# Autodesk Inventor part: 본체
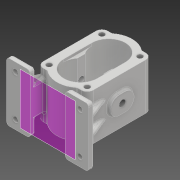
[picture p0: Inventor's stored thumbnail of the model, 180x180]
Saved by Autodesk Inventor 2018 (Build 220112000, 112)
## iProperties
Created: 2023-06
Part Number: 본체
Material: 일반
Document SubType Name: Modeling
Designer: 강의실01
Density: 1 g/cm^3
Appearance: 기본값
Mass: 469.209 g
Surface Area: 986.48 cm^2
Volume: 469.209 cm^3
Author: 강의실01
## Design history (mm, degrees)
sketch "스케치1"
  geometry: L1 (-42.5, -45)-(-42.5, 45); L2 (42.5, 45)-(42.5, -45); L3 (42.5, -55)-(-42.5, 55); L4 (-42.5, -55)-(42.5, 55); L5 (-24, -24)-(24, 24); L6 (24, -24)-(-24, 24); L7 (-32.5, 55)-(-25.278, 55); L8 (25.278, 55)-(32.5, 55); L9 (32.5, -55)-(25.278, -55); L10 (-25.278, -55)-(-32.5, -55); L11 (22.5, 6.507)-(22.5, -6.507); L12 (-22.5, -6.507)-(-22.5, 6.507); L13 (-22.5, 22.5)-(22.5, -22.5); L14 (22.5, 22.5)-(-22.5, -22.5); A1 r 10 centre (-32.5, 45) between (-32.5, 55) and (-42.5, 45); A2 r 10 centre (32.5, 45) between (42.5, 45) and (32.5, 55); A3 r 10 centre (32.5, -45) between (32.5, -55) and (42.5, -45); A4 r 10 centre (-32.5, -45) between (-42.5, -45) and (-32.5, -55); A5 r 40 centre (0, -24) between (-25.278, -55) and (25.278, -55); A6 r 40 centre (0, 24) between (25.278, 55) and (-25.278, 55); A7 r 28.5 centre (0, 24) between (22.5, 6.507) and (-22.5, 6.507); A8 r 28.5 centre (0, -24) between (-22.5, -6.507) and (22.5, -6.507); 1 further point
  constraints: 28 end point, 16 point on circle, 14 tangent, 8 centre point, 6 midpoint, 6 parallel, 5 equal radius, 4 perpendicular, 4 point on line, 2 coincident, 2 collinear, 2 horizontal
  dimensions: "d0" = 85 distance of L3.end L4.end; "d1" = 110 distance of L4.start L3.end; "d2" = 10 radius of A1 (derived); "d3" = 48 distance of L6.end L5.end; "d4" = 48 distance of L5.end L6.start; "d9" = 45 distance of L13.end L14.end; "d10" = 45 distance of L14.start L13.end; "d11" = 40 radius of A6; "d12" = 28.5 radius of A7; "d13" = 45 deg angle of L14 L2; "d14" = 37.6942 deg angle of L4 L2; "d15" = 37.6942 deg angle of L3 L2; "d16" = 110 distance between parallel lines of L10 L8; "d17" = 55 distance from line of point (0, 0) L8; "d18" = 17.22155 distance from line of L8.start L2; "d19" = 17.22155 distance from line of L9.end L2; "d20" = 18.5 distance from line of L5.end L2; "d21" = 20 distance from line of L14.start L2; "d22" = 48.49286 distance from line of L11.start L8; "d23" = 61.50714 distance from line of L11.end L8; "d24" = 65 distance from line of L13.start L2; "d25" = 66.5 distance from line of L5.start L2
extrude "돌출1" new body sketch "스케치1" stored distance "d26" = 79; taper "d27" = 0 deg
sketch "스케치2"
  geometry: L1 (28.5, 24)-(28.5, -24); L2 (-28.5, -24)-(-28.5, 24); L3 (-28.5, 24)-(28.5, 24); L4 (-28.5, -24)-(28.5, -24); A1 r 28.5 centre (0, 24) between (22.5, 6.507) and (-22.5, 6.507) reference; A2 r 28.5 centre (0, -24) between (-22.5, -6.507) and (22.5, -6.507) reference; 1 further point
  constraints: 8 end point, 3 point on circle, 2 vertical, 1 horizontal, 1 perpendicular, 1 tangent
extrude "돌출2" cut sketch "스케치2" distance "d28" = 4.5; taper "d29" = 0 deg
sketch "스케치3"
  geometry: A1 r 10 centre (-32.5, 45) between (-32.5, 55) and (-42.5, 45) reference; A2 r 10 centre (32.5, 45) between (42.5, 45) and (32.5, 55) reference; A3 r 10 centre (32.5, -45) between (32.5, -55) and (42.5, -45) reference; A4 r 10 centre (-32.5, -45) between (-42.5, -45) and (-32.5, -55) reference; 5 further points
  constraints: 4 coincident
hole "구멍1" sketch "스케치3" at (-32.5, 45), (32.5, 45), (32.5, -45), (-32.5, -45) diameter "d30" = 9; stored, may be unused: countersink angle "d34" = 90 deg, drill point angle "d36" = 0 deg; dims "d31" = 6, "d32" = 4, "d33" = 2, "d35" = 79
node "작업 평면1"
sketch "스케치4"
  geometry: L1 (70, -45)-(70, 45); L2 (-70, 45)-(-70, -45); L3 (-70, -50)-(70, 50); L4 (70, -50)-(-70, 50); L5 (-65, -50)-(-35, -50); L6 (-30, -45)-(-30, 45); L7 (-35, 50)-(-65, 50); L8 (-70, 45)-(-70, -45); L9 (65, -50)-(35, -50); L10 (30, -45)-(30, 45); L11 (35, 50)-(65, 50); L12 (70, 45)-(70, -45); L13 (-65, -50)-(-35, -50); L14 (35, -50)-(65, -50); L15 (65, 50)-(35, 50); L16 (-35, 50)-(-65, 50); A1 r 5 centre (65, -45) between (65, -50) and (70, -45); A2 r 5 centre (35, -45) between (30, -45) and (35, -50); A3 r 5 centre (-35, -45) between (-35, -50) and (-30, -45); A4 r 5 centre (-65, -45) between (-70, -45) and (-65, -50); A5 r 5 centre (-65, 45) between (-65, 50) and (-70, 45); A6 r 5 centre (-35, 45) between (-30, 45) and (-35, 50); A7 r 5 centre (35, 45) between (35, 50) and (30, 45); A8 r 5 centre (65, 45) between (70, 45) and (65, 50); 1 further point
  constraints: 32 end point, 17 tangent, 16 point on circle, 9 parallel, 8 centre point, 7 equal radius, 6 point on line, 4 horizontal, 4 perpendicular, 2 midpoint
  dimensions: "d38" = 140 distance of L4.end L3.end; "d39" = 100 distance of L3.end L4.start; "d42" = 54.4623 deg angle of L1 L4; "d43" = 54.4623 deg angle of L3 L12; "d44" = 5 radius of A1; "d45" = 40 distance between parallel lines of L12 L10; "d46" = 40 distance between parallel lines of L2 L6; "d47" = 100 distance between parallel lines of L11 L14
extrude "돌출3" join sketch "스케치4" distance "d48" = 9; taper "d49" = 0 deg
sketch "스케치5" dims "d63" = 10
  geometry: L1 (-30, -45)-(-30, 45) reference; L2 (-30, 0)-(-30, 21); L3 (-30, 0)-(-30, -21); L4 (-34, -25)-(-34, 25); L5 (-30, -21)-(-30, 21); L6 (-38, 21)-(-38, -21); L7 (-34, 0)-(34, 0); L8 (30, 21)-(30, -21); L9 (38, 0)-(38, 21); L10 (38, 0)-(38, -21); L11 (-38, 21)-(-38, 25); L12 (-38, 25)-(-30, 25); L13 (-30, 25)-(-30, 21); L14 (-38, -21)-(-38, -25); L15 (-38, -25)-(-30, -25); L16 (-30, -25)-(-30, -21); L17 (30, -21)-(30, -25); L18 (30, 45)-(30, -45) reference; L19 (30, -25)-(38, -25); L20 (38, -25)-(38, -21); L21 (38, 21)-(38, 25); L22 (38, 25)-(30, 25); L23 (30, 25)-(30, 21); L24 (-38, 25)-(-38, -25); L25 (-30, 25)-(-30, -25); L26 (30, 25)-(30, -25); L27 (38, -25)-(38, 25); A1 r 4 centre (-34, -21) between (-38, -21) and (-30, -21); A2 r 4 centre (-34, 21) between (-30, 21) and (-38, 21); A3 r 4 centre (34, 21) between (38, 21) and (30, 21); A4 r 4 centre (34, -21) between (30, -21) and (38, -21); 1 further point
  constraints: 52 end point, 10 point on circle, 9 tangent, 7 point on line, 4 centre point, 4 perpendicular, 2 collinear, 2 horizontal, 2 midpoint, 2 vertical, 1 parallel, 12 other
  dimensions: "d55" = 50 distance of L4.start L4.end; "d56" = 24 distance of L1.end L2.end; "d57" = 68 distance of L7.start L7.end; "d60" = 68 distance of A2.centre A3.centre; "d85" = 4 distance of L6.start L11.end; "d86" = 8 distance of L11.end L12.end (derived); "d87" = 4 distance of L12.end L2.end (derived); "d88" = 4 distance of L6.end L14.end; "d89" = 8 distance of L14.end L15.end; "d90" = 4 distance of L8.end L17.end; "d91" = 8 distance of L17.end L19.end; "d92" = 4 distance of L9.end L21.end; "d93" = 8 distance of L21.end L22.end (derived)
extrude "돌출4" join sketch "스케치5" stored distance "d65" = 9; taper "d66" = 0 deg
node "작업 평면2"
sketch "스케치7"
  geometry: L1 (-70, -71)-(-62, -71); L2 (-35, -71)-(-65, -71) reference; L3 (-62, -71)-(-42.5, -25.061); L4 (-42.5, -45)-(-42.5, 45) reference; 1 further point
  constraints: 4 end point, 2 point on line
  dimensions: "d68" = 8 distance of L1.start L1.end; "d69" = 113 deg angle of L3 L1
feature "리브1" sketch "스케치7" dims "d70" = 1, "d71" = 7, "d72" = 0, "d73" = 0, "d74" = 1, "d75" = 1
node "작업 평면3"
sketch "스케치8"
  geometry: L1 (-70, -80)-(-70, -71) reference; L2 (-70, -71)-(-62, -71); L3 (-35, -71)-(-65, -71) reference; L4 (-62, -71)-(-42.5, -25.061); L5 (-42.5, -45)-(-42.5, 45) reference; 1 further point
  constraints: 4 end point, 2 point on line
  dimensions: "d77" = 8 distance of L1.end L2.end; "d78" = 113 deg angle of L4 L2
feature "리브2" sketch "스케치8" dims "d79" = 1, "d80" = 7, "d81" = 0, "d82" = 0, "d83" = 1, "d84" = 1
extrude "돌출5" join sketch "스케치5" stored distance "d94" = 9; taper "d95" = 0 deg
sketch "스케치9"
  geometry: L1 (-24.5, 40)-(-24.5, 50); L2 (-54.5, 50)-(-54.5, 40); L3 (-54.5, 40)-(-24.5, 50); L4 (-24.5, 40)-(-54.5, 50); A1 r 15 centre (-39.5, 50) between (-24.5, 50) and (-54.5, 50); A2 r 15 centre (-39.5, 40) between (-54.5, 40) and (-24.5, 40); 1 further point
  constraints: 8 end point, 4 point on circle, 4 tangent, 2 centre point, 2 midpoint, 1 parallel
  dimensions: "d96" = 30 distance of L2.start L1.end; "d97" = 10 distance of L1.end L1.start
extrude "돌출6" join sketch "스케치9" distance "d100" = 5; taper "d101" = 0 deg
sketch "스케치10"
  geometry: L1 (-54.5, 50)-(-54.5, 40) reference; L2 (-24.5, 40)-(-24.5, 50) reference; A1 r 15 centre (-39.5, 40) between (-54.5, 40) and (-24.5, 40) reference; A2 r 15 centre (-39.5, 50) between (-24.5, 50) and (-54.5, 50) reference; 2 further points
  constraints: 1 coincident
hole "구멍2" sketch "스케치10" at (-39.5, 45) diameter "d102" = 10.5; stored, may be unused: countersink angle "d108" = 90 deg, drill point angle "d110" = 0 deg; dims "d103" = 11, "d104" = 0.62479, "d105" = 10.589, "d106" = 4, "d107" = 2, "d109" = 25
sketch "스케치11"
  geometry: L1 (55, 35)-(-55, 35); L2 (-55, 35)-(-55, -35); L3 (-55, -35)-(55, -35); L4 (55, -35)-(55, 35); L5 (55, 35)-(-55, -35); L6 (-55, 35)-(55, -35); C1 r 9 at (55, -35); C2 r 9 at (-55, -35); C3 r 9 at (-55, 35); C4 r 9 at (55, 35); 1 further point
  constraints: 12 end point, 4 centre point, 4 coincident, 2 midpoint, 2 parallel, 1 horizontal, 1 perpendicular
  dimensions: "d111" = 110 distance of L3.end L2.end; "d112" = 70 distance of L2.end L1.end; "d113" = 18 diameter of C1; "d114" = 18 diameter of C2; "d115" = 18 diameter of C3; "d116" = 18 diameter of C4
extrude "돌출7" join sketch "스케치11" distance "d117" = 3; taper "d118" = 0 deg
sketch "스케치12"
  geometry: C1 r 9 at (-110, 0) reference; C2 r 9 at (-110, 70) reference; C3 r 9 at (0, 70) reference; C4 r 9 at (0, 0) reference; 5 further points
  constraints: 4 coincident
hole "구멍3" sketch "스케치12" at (-110, 0), (-110, 70), (0, 70), (0, 0) diameter "d119" = 9; stored, may be unused: countersink angle "d123" = 90 deg, drill point angle "d125" = 0 deg; dims "d120" = 11, "d121" = 4, "d122" = 2, "d124" = 25
node "작업 평면4"
sketch "스케치13"
  geometry: 2 further points
  constraints: 1 vertical alignment, 1 other
  dimensions: "d127" = 20 distance of point (0, 0) point (0, -20)
feature "엠보싱1" sketch "스케치13" dims "d0" = 85, "d1" = 110, "d2" = 10 (derived), "d3" = 48, "d4" = 48, "d9" = 45, "d10" = 45, "d11" = 40, "d12" = 28.5, "d13" = 45 deg, "d14" = 6.57889, "d15" = 6.57889, "d16" = 110, "d17" = 55, "d18" = 17.22155, "d19" = 17.22155, "d20" = 18.5, "d21" = 20, "d22" = 48.49286, "d23" = 61.50714, "d24" = 65, "d25" = 66.5, "d128" = 0.5, "d129" = 0
fillet "모깎기1" dims "d130" = 3
fillet "모깎기2" dims "d131" = 3
fillet "모깎기3" dims "d132" = 3
fillet "모깎기4" dims "d133" = 3
node "솔리드1"
mirror "미러1"
mirror "미러2"
mirror "미러3"
mirror "미러4"
node "투영된 루프1"
other parameters: "d7" = 57, "d8" = 57, "d67" = 11, "d76" = -11, "d126" = 144
